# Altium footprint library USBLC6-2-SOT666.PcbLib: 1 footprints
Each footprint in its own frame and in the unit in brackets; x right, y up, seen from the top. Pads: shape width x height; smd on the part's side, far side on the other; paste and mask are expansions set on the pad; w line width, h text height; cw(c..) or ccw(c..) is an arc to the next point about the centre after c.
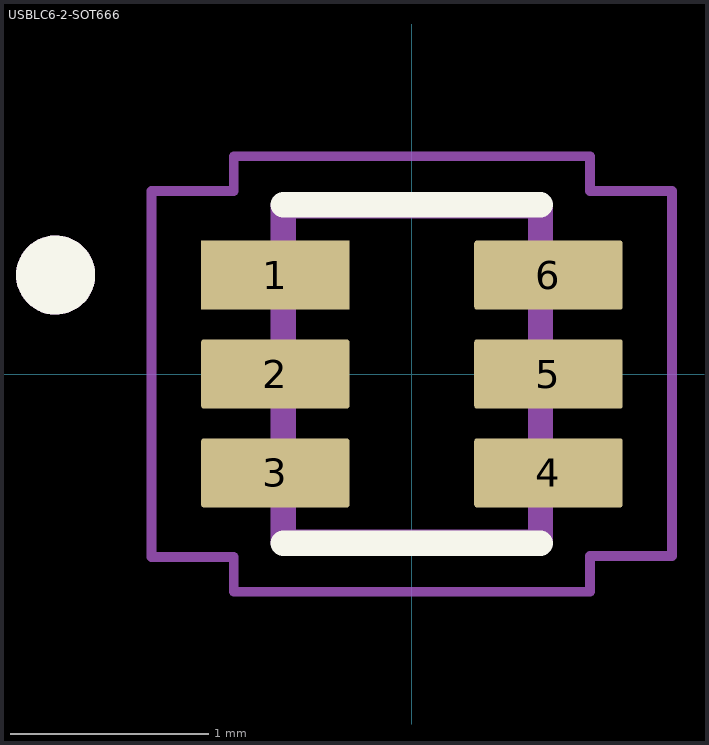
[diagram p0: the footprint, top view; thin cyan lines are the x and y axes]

## USBLC6-2-SOT666 [mm]
pads (6):
  rect 0.75x0.35 smd: 1(-0.69,0.5)
  rrect8% 0.75x0.35 smd: 2(-0.69,0) 3(-0.69,-0.5) 4(0.69,-0.5) 5(0.69,0) 6(0.69,0.5)
Top Overlay:
  circle w0.2: c-1.8,0.5 r0.1
  lines w0.127: -0.65,-0.855 0.65,-0.855 ; -0.65,0.855 0.65,0.855
Mechanical 13:
  circle w0.2: c-1.8,0.5 r0.1
  lines w0.127: -0.65,-0.85 0.65,-0.85 0.65,0.85 -0.65,0.85 -0.65,-0.85
Mechanical 15:
  lines w0.05: -1.315,-0.925 -0.9,-0.925 -0.9,-1.1 0.9,-1.1 0.9,-0.92 1.315,-0.92 1.315,0.925 0.9,0.925 0.9,1.1 -0.9,1.1 -0.9,0.925 -1.315,0.925 -1.315,-0.925
3D body "USBLC6-2-SOT666.STEP": height 0.6, standoff 0, extent -0.82,-0.807 0.78,0.793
